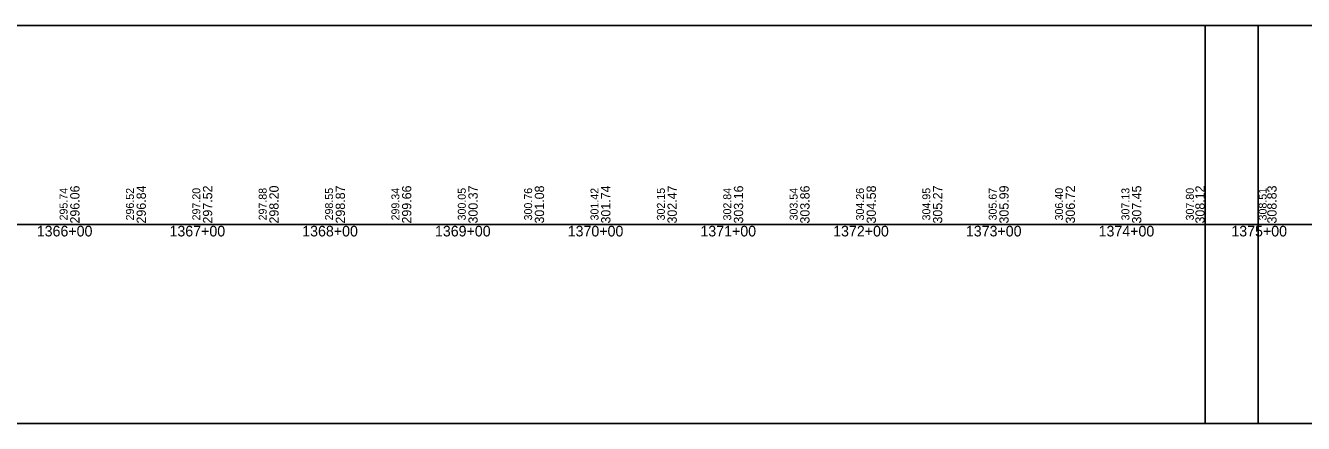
# Model space of a CAD drawing. Extents: x -3627 to 47473, y 2850 to 4350.
# Drawn here: x 24045 to 25007, y 2850 to 3150 of the extents above; entities that cross this region are included whole.
import ezdxf

# ---------------------------------------------------------------- set-up
doc = ezdxf.new("R2010")
doc.units = 0
for name, color, linetype in [('RD_DDB_StaTX', 7, 'Continuous'), ('RD_DDB_StripGrade', 7, 'Continuous'), ('RD_GPK_Profile_Cell', 7, 'Continuous'), ('RD_SHT_ShtClip', 7, 'Continuous')]:
    doc.layers.add(name, color=color, linetype=linetype)

msp = doc.modelspace()

# ---------------------------------------------------------------- linework, layer by layer
at = {"layer": 'RD_GPK_Profile_Cell'}
msp.add_line((1000, 3000), (46705.077602, 3000), dxfattribs=at)
at = {"layer": 'RD_SHT_ShtClip'}
for points in [[(23433.33, 3150), (24973.33, 3150), (24973.33, 2850), (23433.33, 2850)], [(24933.33, 3150), (26473.33, 3150), (26473.33, 2850), (24933.33, 2850)]]:
    msp.add_lwpolyline(points, close=True, dxfattribs=at)

# ---------------------------------------------------------------- texts
at = {"layer": 'RD_DDB_StaTX'}
for s, p in [('1366+00', (24053.125471, 2991)), ('1367+00', (24153.125471, 2991)), ('1368+00', (24253.125471, 2991)), ('1369+00', (24353.125471, 2991)), ('1370+00', (24453.125471, 2991)), ('1371+00', (24553.125471, 2991)), ('1372+00', (24653.125471, 2991)), ('1373+00', (24753.125471, 2991)), ('1374+00', (24853.125471, 2991)), ('1375+00', (24953.125471, 2991))]:
    msp.add_text(s, height=8, dxfattribs=at).set_placement(p)
at = {"layer": 'RD_DDB_StripGrade'}
for s, height, p in [('295.74', 6, (24076.33, 3003.073688)), ('296.06', 7, (24085.33, 3000.75)), ('296.52', 6, (24126.33, 3003.073688)), ('296.84', 7, (24135.33, 3000.75)), ('297.20', 6, (24176.33, 3003.073688)), ('297.52', 7, (24185.33, 3000.75)), ('297.88', 6, (24226.33, 3003.073688)), ('298.20', 7, (24235.33, 3000.75)), ('298.55', 6, (24276.33, 3003.073688)), ('298.87', 7, (24285.33, 3000.75)), ('299.34', 6, (24326.33, 3003.073688)), ('299.66', 7, (24335.33, 3000.75)), ('300.05', 6, (24376.33, 3003.073688)), ('300.37', 7, (24385.33, 3000.75)), ('300.76', 6, (24426.33, 3003.073688)), ('301.08', 7, (24435.33, 3000.75)), ('301.42', 6, (24476.33, 3003.073688)), ('301.74', 7, (24485.33, 3000.75)), ('302.15', 6, (24526.33, 3003.073688)), ('302.47', 7, (24535.33, 3000.75)), ('302.84', 6, (24576.33, 3003.073688)), ('303.16', 7, (24585.33, 3000.75)), ('303.54', 6, (24626.33, 3003.073688)), ('303.86', 7, (24635.33, 3000.75)), ('304.26', 6, (24676.33, 3003.073688)), ('304.58', 7, (24685.33, 3000.75)), ('304.95', 6, (24726.33, 3003.073688)), ('305.27', 7, (24735.33, 3000.75)), ('305.67', 6, (24776.33, 3003.073688)), ('305.99', 7, (24785.33, 3000.75)), ('306.40', 6, (24826.33, 3003.073688)), ('306.72', 7, (24835.33, 3000.75)), ('307.13', 6, (24876.33, 3003.073688)), ('307.45', 7, (24885.33, 3000.75)), ('307.80', 6, (24924.868326, 3003.073688)), ('308.12', 7, (24933.016817, 3000.75)), ('308.51', 6, (24979.707256, 3003.073688)), ('308.83', 7, (24987.201907, 3000.75))]:
    msp.add_text(s, height=height, rotation=90, dxfattribs=at).set_placement(p)

doc.saveas('drawing.dxf')
